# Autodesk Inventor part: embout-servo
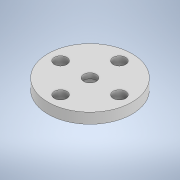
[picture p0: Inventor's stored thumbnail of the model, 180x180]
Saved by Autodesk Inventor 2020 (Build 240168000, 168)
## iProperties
Created: 2021-10
Part Number: embout-servo
Material: Générique
Document SubType Name: Modeling
Designer: bruno
Density: 1 g/cm^3
Appearance: Par défaut
Author: bruno
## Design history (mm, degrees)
sketch "Esquisse1"
  geometry: L1 (0, 0)-(2.5, 0); L2 (2, -4)-(0.5, -4); L3 (0, -3.5)-(0, -2.5); L4 (2.5, 0)-(5, 0); L5 (5, -1.5)-(5, -10); L6 (5, -10)-(2.5, -10); L7 (2.5, -10)-(2.5, -4.5); L8 (3.75, 0)-(0, 0); L9 (0, -1.5)-(0, -2.5); L10 (0, -2.5)-(3.75, -2.5); L11 (3.75, -2.5)-(3.75, -1.5); L12 (3.75, 0)-(5, 0); L13 (5, -1.5)-(3.75, -1.5); A1 r 0.5 centre (0.5, -3.5) between (0, -3.5) and (0.5, -4); A2 r 0.5 centre (2, -4.5) between (2.5, -4.5) and (2, -4)
  constraints: 26 end point, 6 parallel, 4 horizontal, 4 point on circle, 4 tangent, 2 centre point, 2 perpendicular, 2 point on line, 1 equal radius, 1 midpoint
  dimensions: "d0" = 2.5 distance of L5.end L6.end; "d1" = 5 distance between parallel lines of L3 L5; "d2" = 10 distance between parallel lines of L4 L6; "d3" = 4 distance between parallel lines of L1 L2; "d4" = 2.5 distance between parallel lines of L1 L10; "d5" = 0.5 radius of A1; "d11" = 1.5 distance between parallel lines of L12 L13
revolve "Révolution1" sketch "Esquisse1" stored, may be unused: angle "d6" = 90 deg
sketch "Esquisse2"
  geometry: C1 r 1.5 at (0, 7); 1 further point
  constraints: 1 centre point
  dimensions: "d7" = 3 diameter of C1; "d8" = 7 distance of C1.centre point (0, 0)
extrude "Extrusion1" cut sketch "Esquisse2" distance "d9" = 10; taper "d10" = 0 deg
pattern_circular "Réseau circulaire1" dims angle "d13" = 360 deg
node "Solide1"
